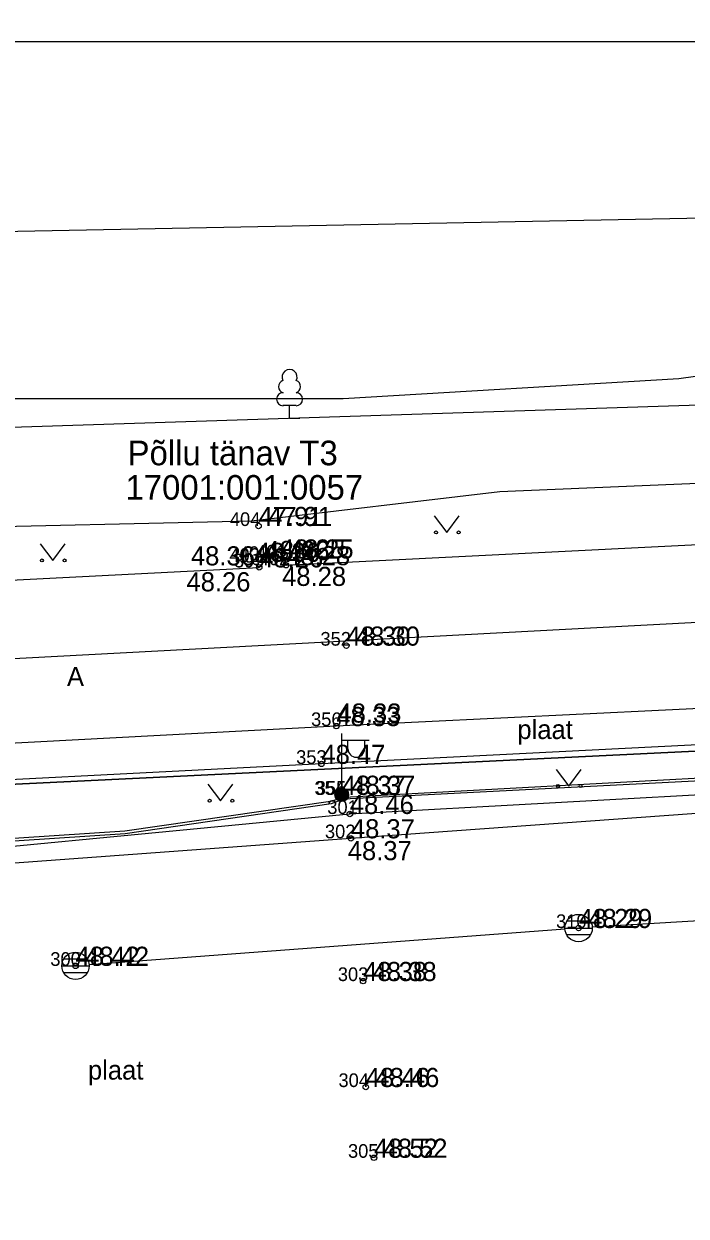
# Model space of a CAD drawing. Extents: x 640876 to 641418, y 6455595 to 6456085.
# Drawn here: x 641105.51 to 641129.76, y 6455977.11 to 6456020.73 of the extents above; entities that cross this region are included whole.
import ezdxf

# ---------------------------------------------------------------- set-up
doc = ezdxf.new("R2010")
doc.units = 0
for name, color, linetype in [('AED', 7, 'Continuous'), ('HALJASTUS', 7, 'Continuous'), ('KORGUS', 7, 'Continuous'), ('MOOTKORG', 7, 'Continuous'), ('MOOTMPUNKT', 7, 'Continuous'), ('MOOTNR', 7, 'Continuous'), ('MOOTPIIR', 7, 'Continuous'), ('MPKAABEL', 7, 'Continuous'), ('PIIR', 7, 'Continuous'), ('POST', 7, 'Continuous'), ('PUU', 7, 'Continuous'), ('SKKAEV', 7, 'Continuous'), ('SKTRASS', 7, 'Continuous'), ('TEE', 7, 'Continuous'), ('VEEKOGU', 7, 'Continuous'), ('VORMISTUS', 7, 'Continuous'), ('VTRASS', 7, 'Continuous')]:
    doc.layers.add(name, color=color, linetype=linetype)

msp = doc.modelspace()

# ---------------------------------------------------------------- linework, layer by layer
at = {"layer": 'AED'}
msp.add_lwpolyline([(641087.994, 6455978.931), (641096.846, 6455989.854), (641117.445, 6455991.822), (641132.506, 6455992.659), (641144.443, 6455993.343), (641153.401, 6455993.722)], dxfattribs=at)
at = {"layer": 'HALJASTUS'}
for p, q in [((641120.539, 6456002.731), (641121.002, 6456002.124)), ((641121.002, 6456002.124), (641121.448, 6456002.731)), ((641106.108, 6456001.705), (641106.571, 6456001.099)), ((641106.571, 6456001.099), (641107.017, 6456001.705)), ((641125.002, 6455993.451), (641125.466, 6455992.845)), ((641125.466, 6455992.845), (641125.911, 6455993.451)), ((641112.25, 6455992.91), (641112.713, 6455992.304)), ((641112.713, 6455992.304), (641113.159, 6455992.91))]:
    msp.add_line(p, q, dxfattribs=at)
for centre in [(641120.601, 6456002.124), (641121.43, 6456002.124), (641106.17, 6456001.099), (641106.999, 6456001.099), (641125.065, 6455992.845), (641125.893, 6455992.845), (641112.312, 6455992.304), (641113.141, 6455992.304)]:
    msp.add_circle(centre, 0.055, dxfattribs=at)
at = {"layer": 'KORGUS'}
for centre in [(641114.103, 6456002.358), (641114.01, 6456001.045), (641114.891, 6456001.167), (641115.111, 6456000.924), (641114.127, 6456000.844), (641117.319, 6455997.98), (641116.951, 6455995.037), (641117.148, 6455992.524), (641117.149, 6455992.522), (641117.484, 6455990.932), (641125.823, 6455987.649), (641107.403, 6455986.266), (641117.931, 6455985.709), (641118.03, 6455981.832), (641118.328, 6455979.243)]:
    msp.add_circle(centre, 0.1, dxfattribs=at)
at = {"layer": 'MOOTMPUNKT'}
for centre in [(641114.103, 6456002.358), (641114.01, 6456001.045), (641114.356, 6456001.115), (641114.891, 6456001.167), (641115.111, 6456000.924), (641114.127, 6456000.844), (641117.319, 6455997.98), (641116.951, 6455995.037), (641116.405, 6455993.654), (641117.148, 6455992.524), (641117.149, 6455992.522), (641117.445, 6455991.822), (641117.484, 6455990.932), (641125.823, 6455987.649), (641107.403, 6455986.266), (641117.931, 6455985.709), (641118.03, 6455981.832), (641118.328, 6455979.243)]:
    msp.add_circle(centre, 0.1, dxfattribs=at)
at = {"layer": 'MOOTPIIR'}
msp.add_lwpolyline([(641060.916, 6455895.936), (641100.061, 6455950.482), (641099.586, 6455952.159), (641069.132, 6455984.035), (641066.132, 6455988.623), (641076.463, 6456005.049), (641230.642, 6456010.048), (641237.36, 6455995.24), (641237.24, 6455992.81), (641236.258, 6455990.888), (641229.041, 6455971.315), (641203.026, 6455909.57), (641225.257, 6455906.847), (641239.512, 6455898.491), (641200.195, 6455851.697), (641192.016, 6455859.099), (641169.785, 6455829.138), (641192.025, 6455807.568), (641252.96, 6455758.075), (641231.388, 6455736.74), (641191.474, 6455775.975), (641152.419, 6455787.914), (641136.351, 6455788.307), (641049.066, 6455856.043)], dxfattribs=at)
at = {"layer": 'MPKAABEL'}
for points in [[(641081.282, 6455986.001), (641083.826, 6455989.191), (641093.656, 6455990.177), (641101.434, 6455990.689), (641109.211, 6455991.201), (641116.735, 6455992.286), (641117.253, 6455992.438), (641137.02, 6455993.508), (641152.446, 6455994.375), (641152.745, 6455994.399), (641153.077, 6455993.956), (641153.192, 6455989.529), (641153.743, 6455971.272), (641153.877, 6455968.765), (641154.087, 6455964.787), (641154.134, 6455960.265)], [(641154.034, 6455960.264), (641153.95, 6455965.518), (641153.778, 6455968.761), (641153.643, 6455971.268), (641153.102, 6455989.126), (641152.978, 6455993.905), (641152.599, 6455994.224), (641152.147, 6455994.252), (641142.791, 6455993.73), (641131.26, 6455993.087), (641117.217, 6455992.367), (641116.76, 6455992.188), (641112.991, 6455991.645), (641109.221, 6455991.101), (641101.443, 6455990.589), (641093.665, 6455990.077), (641088.757, 6455989.569), (641083.848, 6455989.06), (641081.36, 6455985.939)]]:
    msp.add_lwpolyline(points, dxfattribs=at)
at = {"layer": 'PIIR'}
for points in [[(640981.25, 6456014.49), (641018.11, 6456020.73), (641048.89, 6456017.91), (641071.8, 6456014.51), (641086.43, 6456012.78), (641194.48, 6456014.88), (641224.33, 6456016.64), (641234.96, 6456017.83), (641241.97, 6456004.88), (641237.36, 6455995.24), (641222.58, 6455998.61), (641084.84, 6455991.92), (641061.51, 6455993.34), (640998.61, 6455989.99), (640969.54, 6455988.44)], [(641222.58, 6455998.61), (641237.36, 6455995.24), (641235.34, 6455991.29), (641228.11, 6455971.68), (641220.5, 6455953.19), (641213.41, 6455936.25), (641201.58, 6455908.74), (641224.93, 6455905.88), (641191.87, 6455860.58), (641157.02, 6455885.66), (641160.91, 6455891.99), (641102.26, 6455951.82), (641074.95, 6455979.64), (641084.84, 6455991.92)]]:
    msp.add_lwpolyline(points, close=True, dxfattribs=at)
at = {"layer": 'POST'}
for p, q in [((641117.149, 6455992.772), (641117.149, 6455994.772)), ((641117.149, 6455994.522), (641118.149, 6455994.522)), ((641117.376, 6455994.201), (641117.376, 6455994.522)), ((641117.989, 6455994.201), (641117.989, 6455994.522)), ((641117.149, 6455992.522), (641117.149, 6455992.522))]:
    msp.add_line(p, q, dxfattribs=at)
for radius in [0.25, 0.225, 0.2, 0.175, 0.15, 0.125, 0.1, 0.075, 0.05, 0.025]:
    msp.add_circle((641117.148, 6455992.524), radius, dxfattribs=at)
msp.add_arc((641117.682, 6455994.201), 0.306, 180, 0, dxfattribs=at)
at = {"layer": 'PUU'}
for p, q in [((641115.478, 6456006.761), (641114.998, 6456006.761)), ((641115.238, 6456006.286), (641115.238, 6456006.761)), ((641115.618, 6456006.286), (641115.238, 6456006.286))]:
    msp.add_line(p, q, dxfattribs=at)
for centre, radius, start, end in [((641115.238, 6456007.806), 0.277, 332.5799, 207.4201), ((641115.068, 6456007.458), 0.233, 109.0217, 253.1415), ((641115.408, 6456007.458), 0.233, 286.8508, 70.9859), ((641115.001, 6456006.998), 0.238, 90.0016, 269.3953), ((641115.476, 6456006.998), 0.238, 270.6047, 89.9984)]:
    msp.add_arc(centre, radius, start, end, dxfattribs=at)
at = {"layer": 'SKKAEV'}
for p, q in [((641126.253, 6455987.899), (641125.393, 6455987.899)), ((641125.323, 6455987.649), (641126.323, 6455987.649)), ((641126.253, 6455987.399), (641125.393, 6455987.399)), ((641106.903, 6455986.266), (641107.903, 6455986.266)), ((641107.833, 6455986.516), (641106.973, 6455986.516)), ((641107.833, 6455986.016), (641106.973, 6455986.016))]:
    msp.add_line(p, q, dxfattribs=at)
for centre in [(641125.823, 6455987.649), (641107.403, 6455986.266)]:
    msp.add_circle(centre, 0.5, dxfattribs=at)
at = {"layer": 'SKTRASS'}
for points in [[(641143.428, 6455988.697), (641126.323, 6455987.679)], [(641125.325, 6455987.612), (641107.901, 6455986.304)]]:
    msp.add_lwpolyline(points, dxfattribs=at)
at = {"layer": 'TEE'}
for points in [[(641082.336, 6456003.369), (641084.664, 6456001.107), (641086.093, 6456000.303), (641086.838, 6456000.014), (641087.575, 6455999.79), (641088.445, 6455999.722), (641093.981, 6455999.821), (641114.127, 6456000.844), (641114.356, 6456001.115)], [(641114.891, 6456001.167), (641115.111, 6456000.924), (641135.305, 6456001.938), (641156.494, 6456002.943), (641156.781, 6456003.203)], [(641088.432, 6455978.324), (641097.01, 6455989.437), (641117.484, 6455990.932), (641132.837, 6455992.048), (641144.43, 6455992.887), (641153.501, 6455993.325), (641154.822, 6455993.407), (641154.653, 6455994.333), (641154.316, 6455995.079), (641153.74, 6455995.681), (641153.065, 6455996.145), (641151.601, 6455996.628), (641150.727, 6455996.717), (641135.038, 6455995.912), (641116.951, 6455995.037), (641097.835, 6455994.027), (641080.247, 6455993.161), (641080.246, 6455993.162), (641078.083, 6455992.591), (641077.94, 6455991.681), (641080.556, 6455991.837)], [(641153.501, 6455993.325), (641153.465, 6455993.996), (641152.772, 6455994.709), (641151.844, 6455995.148), (641150.896, 6455995.393), (641135.023, 6455994.601), (641116.405, 6455993.654), (641097.851, 6455992.703), (641080.556, 6455991.837)]]:
    msp.add_lwpolyline(points, dxfattribs=at)
at = {"layer": 'VEEKOGU'}
msp.add_lwpolyline([(641139.156, 6456004.288), (641122.94, 6456003.612), (641113.848, 6456002.539), (641102.002, 6456002.261), (641090.12, 6456004.057), (641086.086, 6456005.103), (641084.645, 6456005.811), (641084.269, 6456007.81), (641084.697, 6456009.512), (641086.26, 6456010.646), (641087.438, 6456010.728), (641092.614, 6456009.053), (641103.632, 6456007.017), (641117.202, 6456007.024), (641129.494, 6456007.757), (641140.506, 6456009.297)], dxfattribs=at)
at = {"layer": 'VORMISTUS'}
msp.add_line((641035.115, 6456020.09), (641256.302, 6456020.09), dxfattribs=at)
at = {"layer": 'VTRASS'}
msp.add_lwpolyline([(641064.363, 6455995.75), (641076.979, 6455996.021), (641104.204, 6455997.462), (641127.864, 6455998.715), (641152.811, 6456000.037), (641188.143, 6456001.908), (641203.655, 6456002.73), (641225.036, 6456004.365)], dxfattribs=at)

# ---------------------------------------------------------------- texts
at = {"layer": 'KORGUS'}
for s, p in [('47.91', (641114.453, 6456002.358)), ('48.25', (641115.241, 6456001.167)), ('48.36', (641111.627, 6456000.916)), ('48.26', (641111.464, 6455999.967)), ('48.28', (641114.965, 6456000.166)), ('48.30', (641117.669, 6455997.98)), ('48.33', (641116.992, 6455995.165)), ('48.37', (641117.499, 6455992.522)), ('48.37', (641117.37, 6455990.132)), ('48.29', (641126.173, 6455987.649)), ('48.42', (641107.753, 6455986.266)), ('48.38', (641118.281, 6455985.709)), ('48.46', (641118.38, 6455981.832)), ('48.52', (641118.678, 6455979.243))]:
    msp.add_text(s, height=0.7, dxfattribs=at).set_placement(p)
at = {"layer": 'MOOTKORG'}
for s, p in [('47.91', (641114.103, 6456002.358)), ('48.25', (641114.891, 6456001.167)), ('48.36', (641114.01, 6456001.045)), ('48.26', (641114.127, 6456000.844)), ('48.26', (641114.356, 6456001.115)), ('48.28', (641115.111, 6456000.924)), ('48.30', (641117.319, 6455997.98)), ('48.33', (641116.951, 6455995.037)), ('48.47', (641116.405, 6455993.654)), ('48.37', (641117.148, 6455992.524)), ('48.37', (641117.149, 6455992.522)), ('48.46', (641117.445, 6455991.822)), ('48.37', (641117.484, 6455990.932)), ('48.29', (641125.823, 6455987.649)), ('48.42', (641107.403, 6455986.266)), ('48.38', (641117.931, 6455985.709)), ('48.46', (641118.03, 6455981.832)), ('48.52', (641118.328, 6455979.243))]:
    msp.add_text(s, height=0.7, dxfattribs=at).set_placement(p)
at = {"layer": 'MOOTNR'}
for s, p in [('404', (641113.053, 6456002.358)), ('403', (641113.035, 6456001.045)), ('400', (641113.381, 6456001.115)), ('401', (641114.016, 6456001.167)), ('402', (641114.111, 6456000.924)), ('399', (641113.202, 6456000.844)), ('352', (641116.37, 6455997.98)), ('356', (641116.026, 6455995.037)), ('353', (641115.48, 6455993.654)), ('354', (641116.149, 6455992.522)), ('355', (641116.198, 6455992.524)), ('301', (641116.62, 6455991.822)), ('302', (641116.534, 6455990.932)), ('310', (641124.998, 6455987.649)), ('300', (641106.478, 6455986.266)), ('303', (641117.006, 6455985.709)), ('304', (641117.03, 6455981.832)), ('305', (641117.378, 6455979.243))]:
    msp.add_text(s, height=0.5, dxfattribs=at).set_placement(p)
at = {"layer": 'PIIR'}
for s, p in [('Põllu tänav T3', (641109.31, 6456004.58)), ('17001:001:0057', (641109.231, 6456003.322))]:
    msp.add_text(s, height=0.9, rotation=360, dxfattribs=at).set_placement(p)
at = {"layer": 'TEE'}
for s, p in [('A', (641107.088, 6455996.502)), ('plaat', (641123.581, 6455994.564)), ('plaat', (641107.856, 6455982.104))]:
    msp.add_text(s, height=0.7, dxfattribs=at).set_placement(p)

doc.saveas('drawing.dxf')
